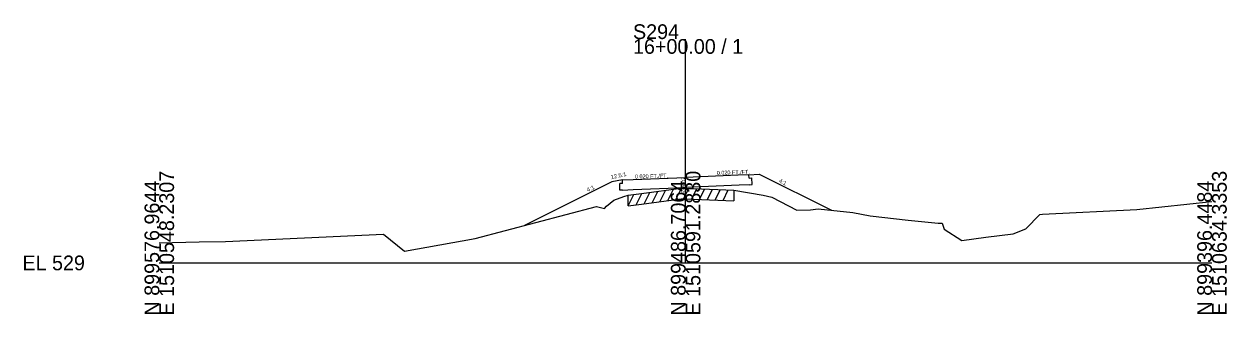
# Model space of a CAD drawing. Extents: x 974 to 2203, y -10 to 19041.
# Drawn here: x 974.3 to 1202.8, y 11990.3 to 12045.3 of the extents above; entities that cross this region are included whole.
import ezdxf

# ---------------------------------------------------------------- set-up
doc = ezdxf.new("R2010")
doc.units = 0
for name, color, linetype in [('RD_GPK_XS_Cell', 7, 'Continuous'), ('RD_XS_Base', 7, 'Continuous'), ('RD_XS_EarthShd', 7, 'Continuous'), ('RD_XS_ExGround', 7, 'Continuous'), ('RD_XS_ExPaveRet', 7, 'Continuous'), ('RD_XS_Pave', 7, 'Continuous'), ('RD_XS_TX_Elev_EX', 7, 'Continuous'), ('RD_XS_TX_Slope', 7, 'Continuous')]:
    doc.layers.add(name, color=color, linetype=linetype)

msp = doc.modelspace()

# ---------------------------------------------------------------- linework, layer by layer
at = {"layer": 'RD_GPK_XS_Cell'}
for p, q in [((1100, 12000), (1100, 12042.5)), ((1000, 12000), (1100, 12000)), ((1100, 12000), (1200, 12000))]:
    msp.add_line(p, q, dxfattribs=at)
at = {"layer": 'RD_XS_Base'}
for p, q in [((1112.05, 12016.11), (1112, 12016.74)), ((1088, 12015.1), (1087.5, 12015.08)), ((1087.5, 12013.81), (1087.5, 12015.08)), ((1088, 12015.1), (1088, 12015.74)), ((1090, 12013.92), (1099.96, 12014.33)), ((1110.16, 12014.76), (1099.96, 12014.33)), ((1112.16, 12014.84), (1110.16, 12014.76)), ((1112.05, 12016.11), (1112.55, 12016.13)), ((1112.16, 12014.84), (1112.66, 12014.86)), ((1112.66, 12014.86), (1112.55, 12016.13)), ((1088, 12013.83), (1087.5, 12013.81)), ((1088, 12013.83), (1090, 12013.92))]:
    msp.add_line(p, q, dxfattribs=at)
at = {"layer": 'RD_XS_EarthShd'}
for p, q in [((1112, 12016.74), (1114, 12016.82)), ((1114, 12016.82), (1127.68, 12009.98)), ((1086, 12015.41), (1069.38, 12007.1)), ((1088, 12015.74), (1086, 12015.41))]:
    msp.add_line(p, q, dxfattribs=at)
at = {"layer": 'RD_XS_ExGround'}
msp.add_lwpolyline([(1000, 12003.81), (1007.59, 12003.99), (1012.59, 12004.07), (1042.58, 12005.46), (1046.6, 12002.22), (1059.99, 12004.61), (1083.05, 12010.72), (1084.6, 12010.34), (1084.97, 12010.8), (1086.38, 12011.92), (1088.23, 12012.59), (1089.11, 12012.84), (1091.64, 12013.15), (1099.16, 12014.17), (1100, 12014.14), (1101.49, 12014.1), (1109.16, 12013.79), (1114.71, 12012.85), (1116.37, 12012.49), (1121.14, 12009.99), (1123.73, 12010.08), (1125.2, 12010.24), (1131.77, 12009.56), (1135.03, 12008.93), (1142.25, 12008.09), (1147.95, 12007.54), (1148.73, 12007.57), (1149.12, 12006.43), (1152.49, 12004.23), (1157.05, 12004.88), (1162.2, 12005.52), (1164.62, 12006.48), (1167.29, 12009.2), (1167.8, 12009.24), (1185.74, 12010.16), (1200, 12011.63)], dxfattribs=at)
at = {"layer": 'RD_XS_ExPaveRet'}
for p, q in [((1096.61, 12011.82), (1097.69, 12013.97)), ((1098.11, 12012.03), (1099.19, 12014.17)), ((1099.61, 12012.16), (1100.6, 12014.13)), ((1101.11, 12012.11), (1102.1, 12014.08)), ((1102.61, 12012.06), (1103.59, 12014.02)), ((1089.11, 12010.84), (1090.18, 12012.97)), ((1089.11, 12010.84), (1089.11, 12012.84)), ((1090.61, 12011.03), (1091.68, 12013.16)), ((1091.64, 12011.15), (1099.16, 12012.17)), ((1092.11, 12011.22), (1093.19, 12013.36)), ((1093.61, 12011.42), (1094.69, 12013.56)), ((1095.11, 12011.62), (1096.19, 12013.77)), ((1099.16, 12012.17), (1100, 12012.14)), ((1100, 12012.14), (1101.49, 12012.1)), ((1101.49, 12012.1), (1109.16, 12011.79)), ((1104.11, 12012), (1105.09, 12013.96)), ((1105.61, 12011.94), (1106.59, 12013.9)), ((1107.11, 12011.87), (1108.09, 12013.84)), ((1109.16, 12013.79), (1109.16, 12011.79)), ((1089.11, 12010.84), (1091.64, 12011.15))]:
    msp.add_line(p, q, dxfattribs=at)
at = {"layer": 'RD_XS_Pave'}
for p, q in [((1110, 12016.66), (1100, 12016.24)), ((1112, 12016.74), (1110, 12016.66)), ((1088, 12015.74), (1090, 12015.82)), ((1090, 12015.82), (1100, 12016.24))]:
    msp.add_line(p, q, dxfattribs=at)

# ---------------------------------------------------------------- texts
at = {"layer": 'RD_GPK_XS_Cell'}
for s, p in [('S294', (1090, 12042.5)), ('16+00.00 / 1', (1090, 12039.7)), ('EL 529', (974, 11998.6))]:
    msp.add_text(s, height=2.8, dxfattribs=at).set_placement(p)
for s, p in [('E 1510548.2307', (1002.8, 11990)), ('E 1510591.2830', (1102.8, 11990)), ('E 1510634.3353', (1202.8, 11990)), ('N 899576.9644', (1000, 11990)), ('N 899486.7064', (1100, 11990)), ('N 899396.4484', (1200, 11990))]:
    msp.add_text(s, height=2.8, rotation=90, dxfattribs=at).set_placement(p)
at = {"layer": 'RD_XS_TX_Elev_EX'}
msp.add_text('536.07', height=0.75, rotation=90, dxfattribs=at).set_placement((1100, 12013.13))
at = {"layer": 'RD_XS_TX_Slope'}
for s, height, rotation, p in [('12.5:1', 0.778, 12.7511, (1085.88, 12015.87)), ('0.020 FT./FT.', 0.7518, 1.8449, (1090.38, 12016)), ('0.020 FT./FT.', 0.7518, 2.1396, (1105.93, 12016.7)), ('4:1', 0.778, 26.3688, (1081.44, 12013.44)), ('4:1', 0.778, 333.6312, (1117.62, 12015.33))]:
    msp.add_text(s, height=height, rotation=rotation, dxfattribs=at).set_placement(p)

doc.saveas('drawing.dxf')
